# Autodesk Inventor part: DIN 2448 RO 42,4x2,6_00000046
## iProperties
Created: 2006-03
Part Number: DIN 2448 RO 42,4x2,6_00000046
Material: Default
Document SubType Name: Modeling
Designer: Carlo
Stock Number: DIN 2448 RO 42,4x2,6
Mass: 577.032 g
Surface Area: 4452.08 cm^2
Volume: 577.032 cm^3
Density: 1 g/cm^3
G_L: 1805.000 mm
G_W: 42.400 mm
G_H: 42.400 mm
AFG_Item: 42.4 x 2.6
CSToolsMass: 1.0
CSToolsVolume: 577032.0
CSToolsArea: 4452.0
Author: Carlo
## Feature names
1. AFG_Detailed_DIN 2448 RO 42,4x2,6_00000046 [Extrusion]
2. AFG_Simplified_DIN 2448 RO 42,4x2,6_00000046 [Extrusion]
3. AFG_EndExtrusion_1 [Extrusion]
4. AFG_EndExtrusion_2 [Extrusion]
5. AFG_StartExtrusion_1 [Extrusion]
6. AFG_StartExtrusion_2 [Extrusion]
